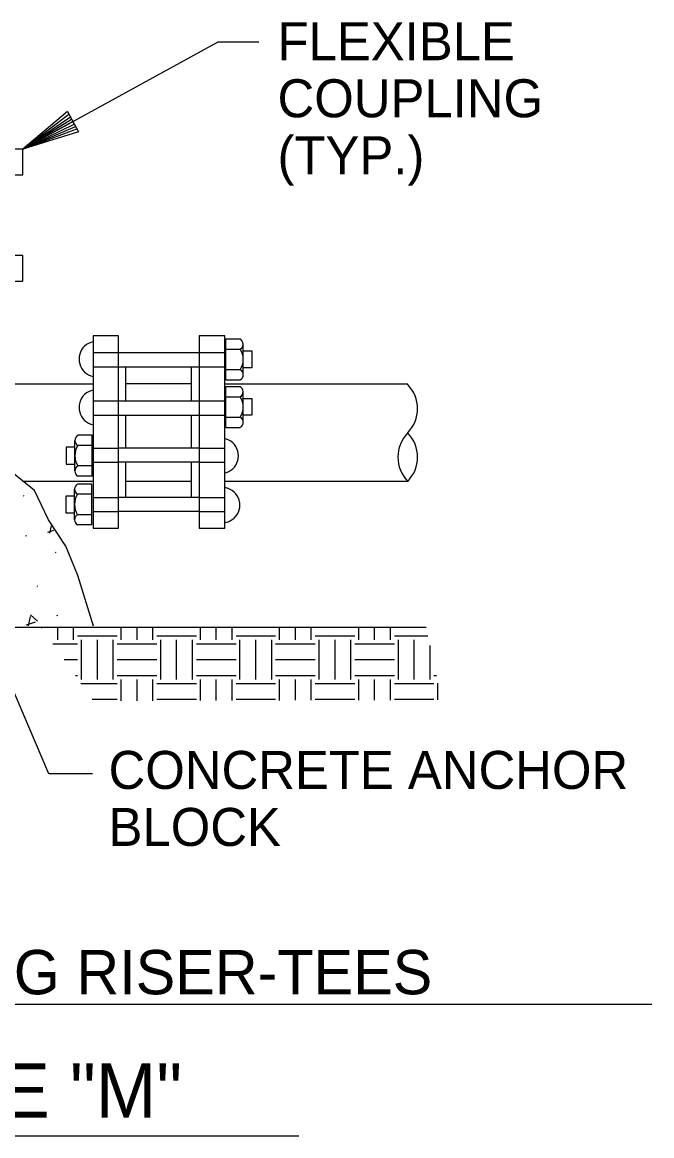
# Model space of a CAD drawing. Extents: x 10040.55 to 10045.84, y 10033.26 to 10035.76.
# Drawn here: x 10041.9653 to 10042.1309, y 10034.3241 to 10034.617 of the extents above; entities that cross this region are included whole.
import ezdxf

# ---------------------------------------------------------------- set-up
doc = ezdxf.new("R2010")
doc.units = 0
doc.layers.add('Level 2', color=7, linetype='Continuous')

msp = doc.modelspace()

# ---------------------------------------------------------------- linework, layer by layer
at = {"layer": 'Level 2'}
for p, q in [((10041.97716, 10034.59352), (10041.96541, 10034.58365)), ((10041.96541, 10034.58365), (10041.97753, 10034.59285)), ((10041.97716, 10034.59352), (10041.98005, 10034.58824)), ((10041.96541, 10034.58365), (10041.97795, 10034.59213)), ((10041.96541, 10034.58365), (10041.97825, 10034.59153)), ((10041.9786, 10034.59092), (10041.96541, 10034.58365)), ((10041.96541, 10034.58365), (10041.97896, 10034.59025)), ((10041.96541, 10034.58365), (10041.97932, 10034.5896)), ((10041.96541, 10034.58365), (10041.97967, 10034.58896)), ((10041.98005, 10034.58824), (10041.96541, 10034.58365)), ((10042.01886, 10034.52297), (10042.01886, 10034.53371)), ((10042.01886, 10034.53371), (10042.02257, 10034.53371)), ((10042.02342, 10034.52432), (10042.02342, 10034.53236)), ((10041.98393, 10034.53013), (10041.99066, 10034.53013)), ((10041.99064, 10034.53013), (10042.01186, 10034.53013)), ((10042.01186, 10034.53013), (10042.01859, 10034.53013)), ((10042.01886, 10034.53103), (10042.0226, 10034.53103)), ((10041.98393, 10034.52641), (10041.99066, 10034.52641)), ((10041.99064, 10034.52641), (10042.01186, 10034.52641)), ((10041.99243, 10034.52641), (10041.99243, 10034.51743)), ((10042.00984, 10034.51743), (10042.00984, 10034.52641)), ((10042.01186, 10034.52641), (10042.01859, 10034.52641)), ((10042.01886, 10034.52564), (10042.0226, 10034.52564)), ((10042.01886, 10034.52297), (10042.0226, 10034.52297)), ((10041.95282, 10034.52191), (10041.98391, 10034.52191)), ((10042.00983, 10034.52193), (10041.99249, 10034.52193)), ((10042.01859, 10034.52191), (10042.06668, 10034.52191)), ((10042.01886, 10034.51046), (10042.01886, 10034.5212)), ((10042.01886, 10034.5212), (10042.02257, 10034.5212)), ((10042.02342, 10034.51181), (10042.02342, 10034.51985)), ((10041.98393, 10034.5174), (10041.99066, 10034.5174)), ((10041.99064, 10034.5174), (10042.01186, 10034.5174)), ((10042.01186, 10034.5174), (10042.01859, 10034.5174)), ((10042.01886, 10034.51852), (10042.0226, 10034.51852)), ((10041.98393, 10034.51368), (10041.99066, 10034.51368)), ((10041.99064, 10034.51368), (10042.01186, 10034.51368)), ((10041.99243, 10034.51369), (10041.99243, 10034.50498)), ((10042.00984, 10034.50498), (10042.00984, 10034.51369)), ((10042.01186, 10034.51368), (10042.01859, 10034.51368)), ((10042.01886, 10034.51313), (10042.0226, 10034.51313)), ((10041.98367, 10034.50836), (10041.97996, 10034.50836)), ((10041.98367, 10034.49763), (10041.98367, 10034.50836)), ((10042.01886, 10034.51046), (10042.0226, 10034.51046)), ((10041.97911, 10034.49898), (10041.97911, 10034.50702)), ((10041.98367, 10034.50569), (10041.97993, 10034.50569)), ((10041.98393, 10034.50499), (10041.99066, 10034.50499)), ((10042.01186, 10034.50499), (10041.99064, 10034.50499)), ((10042.01186, 10034.50499), (10042.01859, 10034.50499)), ((10041.98367, 10034.50029), (10041.97993, 10034.50029)), ((10041.98393, 10034.50127), (10041.99066, 10034.50127)), ((10042.01186, 10034.50127), (10041.99064, 10034.50127)), ((10041.99243, 10034.50124), (10041.99243, 10034.49202)), ((10042.00984, 10034.49202), (10042.00984, 10034.50124)), ((10042.01186, 10034.50127), (10042.01859, 10034.50127)), ((10041.9654, 10034.49629), (10041.98391, 10034.49629)), ((10041.98367, 10034.49763), (10041.97993, 10034.49763)), ((10041.99249, 10034.49629), (10042.00983, 10034.49629)), ((10042.01859, 10034.49628), (10042.06668, 10034.49628)), ((10041.97904, 10034.48616), (10041.97904, 10034.4942)), ((10041.98359, 10034.49554), (10041.97989, 10034.49554)), ((10041.98359, 10034.4848), (10041.98359, 10034.49554)), ((10041.96575, 10034.49234), (10041.96559, 10034.49248)), ((10041.98359, 10034.49286), (10041.97985, 10034.49286)), ((10041.98393, 10034.49202), (10041.99066, 10034.49202)), ((10042.01186, 10034.49202), (10041.99064, 10034.49202)), ((10042.01186, 10034.49202), (10042.01859, 10034.49202)), ((10041.98359, 10034.48747), (10041.97985, 10034.48747)), ((10041.98393, 10034.4883), (10041.99066, 10034.4883)), ((10042.01186, 10034.4883), (10041.99064, 10034.4883)), ((10042.01186, 10034.4883), (10042.01859, 10034.4883)), ((10041.97289, 10034.48454), (10041.97244, 10034.48259)), ((10041.98359, 10034.4848), (10041.97985, 10034.4848)), ((10041.96633, 10034.48186), (10041.96639, 10034.48207)), ((10041.97204, 10034.4829), (10041.97363, 10034.48338)), ((10041.97414, 10034.47749), (10041.97394, 10034.47743)), ((10041.96925, 10034.46879), (10041.9692, 10034.46859)), ((10041.96926, 10034.45945), (10041.96743, 10034.46115)), ((10041.9744, 10034.46096), (10041.97464, 10034.46103)), ((10041.96643, 10034.45852), (10041.96881, 10034.45925)), ((10041.96738, 10034.46068), (10041.96681, 10034.45824)), ((10041.81944, 10034.45785), (10042.07154, 10034.45785)), ((10041.97048, 10034.45758), (10041.97048, 10034.45799)), ((10041.97465, 10034.45456), (10041.97465, 10034.45799)), ((10041.97881, 10034.45456), (10041.97881, 10034.45799)), ((10041.97985, 10034.4556), (10041.99027, 10034.4556)), ((10041.99131, 10034.45456), (10041.99131, 10034.45799)), ((10041.99548, 10034.45456), (10041.99548, 10034.45799)), ((10041.99965, 10034.45456), (10041.99965, 10034.45799)), ((10042.00069, 10034.4556), (10042.0111, 10034.4556)), ((10042.01215, 10034.45456), (10042.01215, 10034.45799)), ((10042.01631, 10034.45456), (10042.01631, 10034.45799)), ((10042.02048, 10034.45456), (10042.02048, 10034.45799)), ((10042.02152, 10034.4556), (10042.03194, 10034.4556)), ((10042.03298, 10034.45456), (10042.03298, 10034.45799)), ((10042.03715, 10034.45456), (10042.03715, 10034.45799)), ((10042.04131, 10034.45456), (10042.04131, 10034.45799)), ((10042.04235, 10034.4556), (10042.05277, 10034.4556)), ((10042.05381, 10034.45456), (10042.05381, 10034.45799)), ((10042.05798, 10034.45456), (10042.05798, 10034.45799)), ((10042.06215, 10034.45456), (10042.06215, 10034.45799)), ((10042.06319, 10034.4556), (10042.07202, 10034.4556)), ((10041.97336, 10034.45352), (10041.97985, 10034.45352)), ((10041.9809, 10034.44415), (10041.9809, 10034.45456)), ((10041.98506, 10034.44415), (10041.98506, 10034.45456)), ((10041.98923, 10034.44415), (10041.98923, 10034.45456)), ((10041.99027, 10034.45352), (10042.00069, 10034.45352)), ((10042.00173, 10034.44415), (10042.00173, 10034.45456)), ((10042.0059, 10034.44415), (10042.0059, 10034.45456)), ((10042.01006, 10034.44415), (10042.01006, 10034.45456)), ((10042.0111, 10034.45352), (10042.02152, 10034.45352)), ((10042.02256, 10034.44415), (10042.02256, 10034.45456)), ((10042.02673, 10034.44415), (10042.02673, 10034.45456)), ((10042.0309, 10034.44415), (10042.0309, 10034.45456)), ((10042.03194, 10034.45352), (10042.04235, 10034.45352)), ((10042.0434, 10034.44415), (10042.0434, 10034.45456)), ((10042.04756, 10034.44415), (10042.04756, 10034.45456)), ((10042.05173, 10034.44415), (10042.05173, 10034.45456)), ((10042.05277, 10034.45352), (10042.06319, 10034.45352)), ((10042.06423, 10034.44415), (10042.06423, 10034.45456)), ((10042.0684, 10034.44415), (10042.0684, 10034.45456)), ((10042.07256, 10034.44415), (10042.07256, 10034.45302)), ((10041.97631, 10034.44935), (10041.97985, 10034.44935)), ((10041.99027, 10034.44935), (10042.00069, 10034.44935)), ((10042.0111, 10034.44935), (10042.02152, 10034.44935)), ((10042.03194, 10034.44935), (10042.04235, 10034.44935)), ((10042.05277, 10034.44935), (10042.06319, 10034.44935)), ((10041.97926, 10034.44519), (10041.97985, 10034.44519)), ((10041.99027, 10034.44519), (10042.00069, 10034.44519)), ((10041.99131, 10034.4385), (10041.99131, 10034.44415)), ((10041.99548, 10034.43851), (10041.99548, 10034.44415)), ((10041.99965, 10034.43853), (10041.99965, 10034.44415)), ((10042.0111, 10034.44519), (10042.02152, 10034.44519)), ((10042.01215, 10034.43856), (10042.01215, 10034.44415)), ((10042.01631, 10034.43857), (10042.01631, 10034.44415)), ((10042.02048, 10034.43859), (10042.02048, 10034.44415)), ((10042.03194, 10034.44519), (10042.04235, 10034.44519)), ((10042.03298, 10034.43863), (10042.03298, 10034.44415)), ((10042.03715, 10034.43864), (10042.03715, 10034.44415)), ((10042.04131, 10034.43866), (10042.04131, 10034.44415)), ((10042.05277, 10034.44519), (10042.06319, 10034.44519)), ((10042.05381, 10034.43869), (10042.05381, 10034.44415)), ((10042.05798, 10034.4387), (10042.05798, 10034.44415)), ((10042.06215, 10034.43872), (10042.06215, 10034.44415)), ((10042.0736, 10034.44519), (10042.07422, 10034.44519)), ((10041.98074, 10034.4431), (10041.99027, 10034.4431)), ((10042.00069, 10034.4431), (10042.0111, 10034.4431)), ((10042.02152, 10034.4431), (10042.03194, 10034.4431)), ((10042.04235, 10034.4431), (10042.05277, 10034.4431)), ((10042.06319, 10034.4431), (10042.0736, 10034.4431)), ((10042.07465, 10034.43875), (10042.07465, 10034.44316)), ((10041.9837, 10034.43894), (10041.99027, 10034.43894)), ((10042.00069, 10034.43894), (10042.0111, 10034.43894)), ((10042.02152, 10034.43894), (10042.03194, 10034.43894)), ((10042.04235, 10034.43894), (10042.05277, 10034.43894)), ((10042.06319, 10034.43894), (10042.0736, 10034.43894)), ((10041.78739, 10034.35869), (10042.13088, 10034.35869)), ((10041.89436, 10034.32407), (10042.03807, 10034.32407))]:
    msp.add_line(p, q, dxfattribs=at)
for points in [[(10042.02749, 10034.61182), (10042.01672, 10034.61182), (10041.96541, 10034.58365)], [(10041.98391, 10034.53298), (10041.98332, 10034.53282), (10041.98274, 10034.53256), (10041.9822, 10034.53224), (10041.9817, 10034.53183), (10041.98126, 10034.53138), (10041.9809, 10034.53085), (10041.9806, 10034.53028), (10041.98039, 10034.52969), (10041.98026, 10034.52906), (10041.98022, 10034.52843), (10041.98026, 10034.52779), (10041.98039, 10034.52717), (10041.9806, 10034.52656), (10041.9809, 10034.526), (10041.98126, 10034.52548), (10041.9817, 10034.52502), (10041.9822, 10034.52461), (10041.98274, 10034.52428), (10041.98332, 10034.52403), (10041.98391, 10034.52388)], [(10042.02344, 10034.53055), (10042.0257, 10034.53055), (10042.0257, 10034.52615), (10042.02344, 10034.52615)], [(10041.98391, 10034.52025), (10041.98332, 10034.52009), (10041.98274, 10034.51983), (10041.9822, 10034.51951), (10041.9817, 10034.5191), (10041.98126, 10034.51865), (10041.9809, 10034.51813), (10041.9806, 10034.51755), (10041.98039, 10034.51696), (10041.98026, 10034.51633), (10041.98022, 10034.5157), (10041.98026, 10034.51506), (10041.98039, 10034.51444), (10041.9806, 10034.51383), (10041.9809, 10034.51327), (10041.98126, 10034.51275), (10041.9817, 10034.51229), (10041.9822, 10034.51189), (10041.98274, 10034.51155), (10041.98332, 10034.5113), (10041.98391, 10034.51115)], [(10042.02344, 10034.51804), (10042.0257, 10034.51804), (10042.0257, 10034.51364), (10042.02344, 10034.51364)], [(10041.98406, 10034.45819), (10041.97995, 10034.47145), (10041.97674, 10034.47923), (10041.97217, 10034.48609), (10041.96851, 10034.49388), (10041.96165, 10034.49936), (10041.94975, 10034.50577), (10041.93923, 10034.50577), (10041.93099, 10034.50622), (10041.92275, 10034.50348), (10041.91406, 10034.49936), (10041.9072, 10034.49113), (10041.90171, 10034.48152), (10041.89714, 10034.47191), (10041.89422, 10034.45785)], [(10041.97909, 10034.50521), (10041.97683, 10034.50521), (10041.97683, 10034.5008), (10041.97909, 10034.5008)], [(10042.01859, 10034.49845), (10042.01905, 10034.49857), (10042.01964, 10034.49882), (10042.02019, 10034.49916), (10042.02068, 10034.49956), (10042.02111, 10034.50002), (10042.02148, 10034.50054), (10042.02177, 10034.5011), (10042.02199, 10034.50171), (10042.02211, 10034.50233), (10042.02217, 10034.50297), (10042.02211, 10034.5036), (10042.02199, 10034.50423), (10042.02177, 10034.50483), (10042.02148, 10034.5054), (10042.02111, 10034.50592), (10042.02068, 10034.50638), (10042.02019, 10034.50678), (10042.01964, 10034.5071), (10042.01905, 10034.50736), (10042.01859, 10034.50749)], [(10042.01859, 10034.48539), (10042.01942, 10034.4856), (10042.02, 10034.48585), (10042.02054, 10034.48619), (10042.02104, 10034.48659), (10042.02147, 10034.48705), (10042.02184, 10034.48757), (10042.02214, 10034.48814), (10042.02235, 10034.48874), (10042.02248, 10034.48936), (10042.02252, 10034.49), (10042.02248, 10034.49064), (10042.02235, 10034.49126), (10042.02214, 10034.49185), (10042.02184, 10034.49243), (10042.02147, 10034.49295), (10042.02104, 10034.49341), (10042.02054, 10034.49381), (10042.02, 10034.49414), (10042.01942, 10034.4944), (10042.01859, 10034.49461)], [(10041.97902, 10034.49239), (10041.97676, 10034.49239), (10041.97676, 10034.48798), (10041.97902, 10034.48798)], [(10041.98373, 10034.41927), (10041.97228, 10034.41927), (10041.95613, 10034.45697)]]:
    msp.add_lwpolyline(points, dxfattribs=at)
for points in [[(10041.91474, 10034.57692), (10041.96541, 10034.57692), (10041.96541, 10034.58365), (10041.91474, 10034.58365)], [(10041.91474, 10034.54896), (10041.96541, 10034.54896), (10041.96541, 10034.55569), (10041.91474, 10034.55569)], [(10041.98391, 10034.53455), (10041.98391, 10034.48389), (10041.99064, 10034.48389), (10041.99064, 10034.53455)], [(10042.01186, 10034.53455), (10042.01186, 10034.48389), (10042.01859, 10034.48389), (10042.01859, 10034.53455)]]:
    msp.add_lwpolyline(points, close=True, dxfattribs=at)
for centre, radius, start, end in [((10042.0219, 10034.53236), 0.0015, 298.1609, 63.2173), ((10042.01846, 10034.52833), 0.00496, 327.057, 32.9938), ((10042.02192, 10034.5243), 0.0015, 297.9658, 62.1123), ((10042.0219, 10034.51985), 0.0015, 298.1609, 63.2173), ((10042.06008, 10034.51538), 0.00918, 315.9775, 44.0212), ((10042.01846, 10034.51582), 0.00496, 327.057, 32.9938), ((10042.02192, 10034.51179), 0.0015, 297.9658, 62.1123), ((10041.98063, 10034.50702), 0.0015, 116.7827, 241.8391), ((10042.07328, 10034.50262), 0.00918, 135.9775, 224.0212), ((10042.06008, 10034.50262), 0.00918, 315.9788, 44.0225), ((10041.98408, 10034.50299), 0.00496, 147.0062, 212.943), ((10041.98062, 10034.49896), 0.0015, 117.8877, 242.0342), ((10041.98055, 10034.49419), 0.0015, 116.7827, 241.8391), ((10041.984, 10034.49016), 0.00496, 147.0062, 212.943), ((10041.98054, 10034.48614), 0.0015, 117.8877, 242.0342)]:
    msp.add_arc(centre, radius, start, end, dxfattribs=at)

# ---------------------------------------------------------------- texts
for s, height, p in [('FLEXIBLE', 0.01, (10042.03244, 10034.60704)), ('COUPLING', 0.01, (10042.03244, 10034.59204)), ('(TYP.)', 0.01, (10042.03244, 10034.57704)), ('CONCRETE ANCHOR', 0.01, (10041.98799, 10034.41532)), ('BLOCK', 0.01, (10041.98799, 10034.40032)), ('UNDERGROUND PIPING RISER-TEES', 0.0116667, (10041.79317, 10034.36128)), ('FIGURE "M"', 0.014301, (10041.90029, 10034.3288))]:
    msp.add_text(s, height=height, dxfattribs=at).set_placement(p)

doc.saveas('drawing.dxf')
